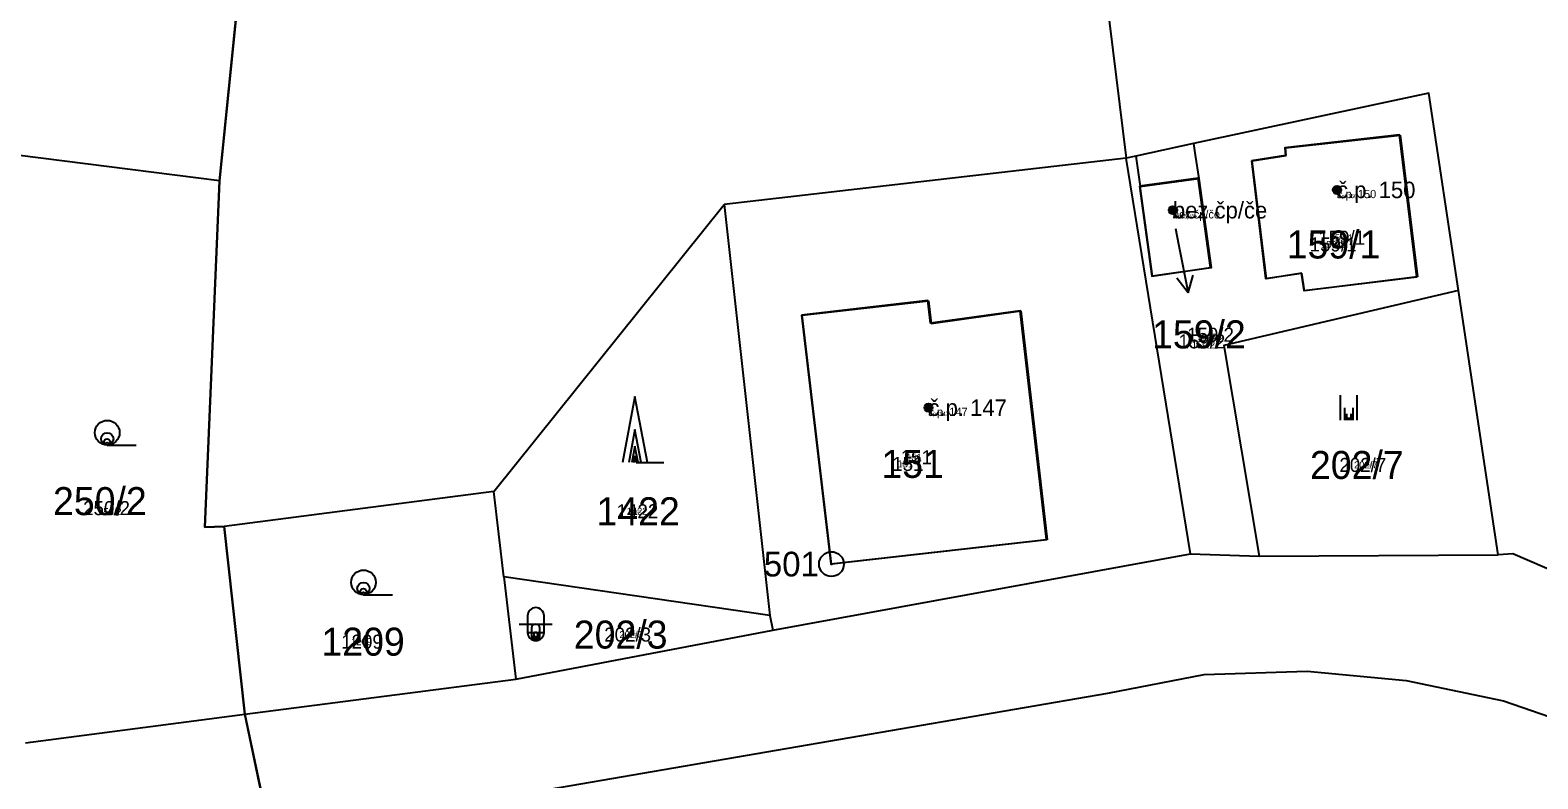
# Model space of a CAD drawing. Extents: x -744652 to -739090, y -980828 to -975855.
# Drawn here: x -741846.2 to -741754.7, y -978833.9 to -978788.5 of the extents above; entities that cross this region are included whole.
import ezdxf

# ---------------------------------------------------------------- set-up
doc = ezdxf.new("R2010")
doc.units = 0
for name, color, linetype in [('KAT_01_hranice KU', 7, 'Continuous'), ('KAT_02_hranice parcel', 7, 'Continuous'), ('KAT_03_1000_st čísla parcelní', 7, 'Continuous'), ('KAT_03_1000_čísla parcelní', 7, 'Continuous'), ('KAT_03_1000_čísla popisná', 7, 'Continuous'), ('KAT_03_100_st čísla parcelní', 7, 'Continuous'), ('KAT_03_100_čísla parcelní', 7, 'Continuous'), ('KAT_03_100_čísla popisná', 7, 'Continuous'), ('KAT_03_250_st čísla parcelní', 7, 'Continuous'), ('KAT_03_250_čísla parcelní', 7, 'Continuous'), ('KAT_03_250_čísla popisná', 7, 'Continuous'), ('KAT_03_500_st čísla parcelní', 7, 'Continuous'), ('KAT_03_500_čísla parcelní', 7, 'Continuous'), ('KAT_03_500_čísla popisná', 7, 'Continuous'), ('KAT_04_vnitřní kresba', 7, 'Continuous'), ('KAT_05_1000_značky kultur', 7, 'Continuous'), ('KAT_05_100_značky kultur', 7, 'Continuous'), ('KAT_05_250_značky kultur', 7, 'Continuous'), ('KAT_05_500_značky kultur', 7, 'Continuous'), ('KAT_07_1000_značky budov', 7, 'Continuous'), ('KAT_07_100_značky budov', 7, 'Continuous'), ('KAT_07_500_značky budov', 7, 'Continuous'), ('KAT_11_značky bodu BP', 7, 'Continuous'), ('KAT_13_popis', 7, 'Continuous'), ('KAT_14_plocha_budovy', 7, 'Continuous')]:
    doc.layers.add(name, color=color, linetype=linetype)

msp = doc.modelspace()

# ---------------------------------------------------------------- linework, layer by layer
at = {"layer": 'KAT_01_hranice KU'}
msp.add_lwpolyline([(-741798.65, -978597.08), (-741808.54, -978644.45), (-741817.44, -978673.77), (-741828.59, -978738.33), (-741829.25, -978742.15), (-741829.42, -978745.8), (-741834.68, -978797.61), (-741835.56, -978818.63), (-741834.39, -978818.59), (-741833.13, -978829.98), (-741831.56, -978837.44), (-741800.71, -978841.57), (-741798.32, -978841.89), (-741797.81, -978844.85), (-741797.75, -978845.17), (-741797.19, -978848.44), (-741793.33, -978870.82), (-741772.86, -978867.41), (-741736.53, -978877.84), (-741709.02, -978891.15), (-741724.37, -978911.25)], dxfattribs=at)
at = {"layer": 'KAT_02_hranice parcel'}
for p, q in [((-741786.56, -978740.39), (-741779.66, -978796.25)), ((-741834.68, -978797.61), (-741829.42, -978745.8)), ((-741834.68, -978797.61), (-741829.42, -978745.8)), ((-741834.68, -978797.61), (-741850.09, -978795.66)), ((-741779.66, -978796.25), (-741804.04, -978799.05)), ((-741775.75, -978820.24), (-741779.66, -978796.25)), ((-741818.02, -978816.47), (-741804.04, -978799.05)), ((-741804.04, -978799.05), (-741801.28, -978823.99)), ((-741757.09, -978820.31), (-741759.49, -978804.27)), ((-741818.02, -978816.47), (-741834.39, -978818.59)), ((-741817.41, -978821.65), (-741818.02, -978816.47)), ((-741833.13, -978829.98), (-741834.39, -978818.59)), ((-741833.13, -978829.98), (-741834.39, -978818.59)), ((-741801.09, -978824.87), (-741775.75, -978820.24)), ((-741775.75, -978820.24), (-741771.59, -978820.39)), ((-741771.59, -978820.39), (-741757.09, -978820.31)), ((-741817.41, -978821.65), (-741816.69, -978827.85)), ((-741801.28, -978823.99), (-741817.41, -978821.65)), ((-741801.28, -978823.99), (-741801.09, -978824.87)), ((-741816.69, -978827.85), (-741801.09, -978824.87)), ((-741833.13, -978829.98), (-741816.69, -978827.85)), ((-741846.45, -978831.72), (-741833.13, -978829.98)), ((-741831.56, -978837.44), (-741833.13, -978829.98)), ((-741831.56, -978837.44), (-741833.13, -978829.98))]:
    msp.add_line(p, q, dxfattribs=at)
for points in [[(-741759.49, -978804.27), (-741761.28, -978792.31), (-741775.56, -978795.36), (-741779.07, -978796.12), (-741779.66, -978796.25)], [(-741834.39, -978818.59), (-741835.56, -978818.63), (-741834.68, -978797.61)], [(-741834.39, -978818.59), (-741835.56, -978818.63), (-741834.68, -978797.61)], [(-741778.06, -978803.41), (-741778.8, -978797.96), (-741775.25, -978797.47), (-741774.49, -978802.89), (-741778.06, -978803.41)], [(-741759.49, -978804.27), (-741773.73, -978807.6), (-741771.59, -978820.39)], [(-741747.63, -978824.34), (-741749.39, -978823.17), (-741756.2, -978820.25), (-741757.09, -978820.31)], [(-741831.56, -978837.44), (-741780.77, -978828.69), (-741774.92, -978827.57), (-741768.67, -978827.36), (-741762.67, -978827.93), (-741756.75, -978829.17), (-741751.07, -978831.13), (-741745.75, -978833.78), (-741726.34, -978844.96)]]:
    msp.add_lwpolyline(points, dxfattribs=at)
at = {"layer": 'KAT_03_1000_čísla popisná'}
for centre in [(-741766.86, -978798.17), (-741776.82, -978799.4), (-741791.65, -978811.38)]:
    msp.add_circle(centre, 0.25, dxfattribs=at)
at = {"layer": 'KAT_03_100_čísla popisná'}
for centre in [(-741766.86, -978798.17), (-741776.82, -978799.4), (-741791.65, -978811.38)]:
    msp.add_circle(centre, 0.025, dxfattribs=at)
at = {"layer": 'KAT_03_250_čísla popisná'}
for centre in [(-741766.86, -978798.17), (-741776.82, -978799.4), (-741791.65, -978811.38)]:
    msp.add_circle(centre, 0.0625, dxfattribs=at)
at = {"layer": 'KAT_03_500_čísla popisná'}
for centre in [(-741766.86, -978798.17), (-741776.82, -978799.4), (-741791.65, -978811.38)]:
    msp.add_circle(centre, 0.125, dxfattribs=at)
at = {"layer": 'KAT_04_vnitřní kresba'}
for p, q in [((-741769.98, -978795.62), (-741763.03, -978794.84)), ((-741763.03, -978794.84), (-741761.97, -978803.45)), ((-741775.56, -978795.36), (-741775.47, -978796.06)), ((-741769.94, -978796.09), (-741769.98, -978795.62)), ((-741779.07, -978796.12), (-741779.01, -978796.55)), ((-741779.01, -978796.55), (-741778.8, -978797.96)), ((-741775.47, -978796.06), (-741775.25, -978797.47)), ((-741772, -978796.41), (-741769.94, -978796.09)), ((-741771.15, -978803.56), (-741772, -978796.41)), ((-741769, -978803.23), (-741771.15, -978803.56)), ((-741768.84, -978804.29), (-741769, -978803.23)), ((-741761.97, -978803.45), (-741768.84, -978804.29)), ((-741799.31, -978805.77), (-741791.64, -978804.89)), ((-741791.64, -978804.89), (-741791.48, -978806.27)), ((-741797.54, -978820.87), (-741799.31, -978805.77)), ((-741791.48, -978806.27), (-741786.04, -978805.51)), ((-741786.04, -978805.51), (-741784.45, -978819.39)), ((-741784.45, -978819.39), (-741797.54, -978820.87))]:
    msp.add_line(p, q, dxfattribs=at)
at = {"layer": 'KAT_05_1000_značky kultur'}
for p, q in [((-741766.641, -978812.13), (-741766.641, -978810.63)), ((-741765.64, -978812.13), (-741765.64, -978810.63)), ((-741809.46, -978810.71), (-741810.21, -978814.71)), ((-741808.71, -978814.71), (-741809.46, -978810.71)), ((-741841.483, -978813.65), (-741839.733, -978813.65)), ((-741808.71, -978814.71), (-741807.714, -978814.71)), ((-741825.933, -978822.73), (-741824.183, -978822.73)), ((-741815.981, -978824.011), (-741815.981, -978825.012)), ((-741814.979, -978825.012), (-741814.979, -978824.011)), ((-741816.481, -978824.511), (-741814.479, -978824.511))]:
    msp.add_line(p, q, dxfattribs=at)
for centre in [(-741841.483, -978812.9), (-741825.933, -978821.98)]:
    msp.add_circle(centre, 0.75, dxfattribs=at)
for centre, start, end in [((-741815.48, -978824.011), 0, 180), ((-741815.48, -978825.011), 180, 359.98789)]:
    msp.add_arc(centre, 0.5, start, end, dxfattribs=at)
at = {"layer": 'KAT_05_100_značky kultur'}
for p, q in [((-741766.181, -978812.13), (-741766.181, -978811.98)), ((-741766.081, -978812.13), (-741766.081, -978811.98)), ((-741841.489, -978813.65), (-741841.314, -978813.65)), ((-741809.46, -978814.31), (-741809.535, -978814.71)), ((-741809.385, -978814.71), (-741809.46, -978814.31)), ((-741809.385, -978814.71), (-741809.285, -978814.71)), ((-741825.939, -978822.73), (-741825.764, -978822.73)), ((-741815.58, -978825.41), (-741815.38, -978825.41)), ((-741815.53, -978825.36), (-741815.53, -978825.46)), ((-741815.43, -978825.46), (-741815.43, -978825.36))]:
    msp.add_line(p, q, dxfattribs=at)
for centre in [(-741841.489, -978813.575), (-741825.939, -978822.655)]:
    msp.add_circle(centre, 0.075, dxfattribs=at)
for centre, start, end in [((-741815.48, -978825.36), 0, 180), ((-741815.48, -978825.46), 180, 359.98789)]:
    msp.add_arc(centre, 0.05, start, end, dxfattribs=at)
at = {"layer": 'KAT_05_250_značky kultur'}
for p, q in [((-741766.258, -978812.13), (-741766.258, -978811.755)), ((-741766.008, -978812.13), (-741766.008, -978811.755)), ((-741841.488, -978813.65), (-741841.051, -978813.65)), ((-741809.46, -978813.71), (-741809.647, -978814.71)), ((-741809.272, -978814.71), (-741809.46, -978813.71)), ((-741809.272, -978814.71), (-741809.024, -978814.71)), ((-741825.938, -978822.73), (-741825.501, -978822.73)), ((-741815.73, -978825.26), (-741815.23, -978825.26)), ((-741815.605, -978825.135), (-741815.605, -978825.385)), ((-741815.355, -978825.385), (-741815.355, -978825.135))]:
    msp.add_line(p, q, dxfattribs=at)
for centre in [(-741841.488, -978813.462), (-741825.938, -978822.542)]:
    msp.add_circle(centre, 0.187, dxfattribs=at)
for centre, start, end in [((-741815.48, -978825.135), 0, 180), ((-741815.48, -978825.385), 180, 359.98789)]:
    msp.add_arc(centre, 0.125, start, end, dxfattribs=at)
at = {"layer": 'KAT_05_500_značky kultur'}
for p, q in [((-741766.385, -978812.13), (-741766.385, -978811.38)), ((-741765.885, -978812.13), (-741765.885, -978811.38)), ((-741809.46, -978812.71), (-741809.835, -978814.71)), ((-741809.085, -978814.71), (-741809.46, -978812.71)), ((-741841.486, -978813.65), (-741840.611, -978813.65)), ((-741809.085, -978814.71), (-741808.587, -978814.71)), ((-741825.937, -978822.73), (-741825.062, -978822.73)), ((-741815.981, -978825.01), (-741814.98, -978825.01)), ((-741815.731, -978824.76), (-741815.731, -978825.261)), ((-741815.23, -978825.261), (-741815.23, -978824.76))]:
    msp.add_line(p, q, dxfattribs=at)
for centre in [(-741841.486, -978813.275), (-741825.936, -978822.355)]:
    msp.add_circle(centre, 0.375, dxfattribs=at)
for centre, start, end in [((-741815.48, -978824.76), 0, 180), ((-741815.48, -978825.26), 180, 359.98789)]:
    msp.add_arc(centre, 0.25, start, end, dxfattribs=at)
at = {"layer": 'KAT_07_1000_značky budov'}
for centre in [(-741766.867, -978798.169), (-741776.827, -978799.399), (-741791.657, -978811.379)]:
    msp.add_circle(centre, 0.175, dxfattribs=at)
at = {"layer": 'KAT_07_100_značky budov'}
for centre in [(-741766.861, -978798.17), (-741776.821, -978799.4), (-741791.651, -978811.38)]:
    msp.add_circle(centre, 0.0175, dxfattribs=at)
at = {"layer": 'KAT_07_500_značky budov'}
for centre in [(-741766.863, -978798.17), (-741776.823, -978799.4), (-741791.653, -978811.38)]:
    msp.add_circle(centre, 0.0875, dxfattribs=at)
at = {"layer": 'KAT_11_značky bodu BP'}
for radius in [0.75, 0.03]:
    msp.add_circle((-741797.54, -978820.87), radius, dxfattribs=at)
at = {"layer": 'KAT_13_popis'}
for p, q in [((-741776.66, -978800.51), (-741776.47, -978801.47)), ((-741776.47, -978801.47), (-741775.897, -978804.416)), ((-741775.897, -978804.416), (-741775.597, -978803.337)), ((-741775.897, -978804.416), (-741776.58, -978803.528))]:
    msp.add_line(p, q, dxfattribs=at)
at = {"layer": 'KAT_14_plocha_budovy'}
for points in [[(-741772.041, -978796.399), (-741771.191, -978803.549), (-741769.041, -978803.219), (-741768.881, -978804.279), (-741762.011, -978803.439), (-741763.071, -978794.829), (-741770.021, -978795.609), (-741769.981, -978796.079)], [(-741778.841, -978797.949), (-741778.101, -978803.399), (-741774.531, -978802.879), (-741775.291, -978797.459)], [(-741799.351, -978805.759), (-741797.581, -978820.859), (-741784.491, -978819.379), (-741786.081, -978805.499), (-741791.521, -978806.259), (-741791.681, -978804.879)]]:
    msp.add_lwpolyline(points, close=True, dxfattribs=at)

# ---------------------------------------------------------------- texts
at = {"layer": 'KAT_03_1000_st čísla parcelní'}
for s, p in [('159/1', (-741769.915, -978802.33)), ('159/2', (-741778.085, -978807.784)), ('151', (-741794.506, -978815.64))]:
    msp.add_text(s, height=1.7, dxfattribs=at).set_placement(p)
at = {"layer": 'KAT_03_1000_čísla parcelní'}
for s, p in [('202/7', (-741768.503, -978815.706)), ('250/2', (-741844.773, -978817.9)), ('1422', (-741811.797, -978818.516)), ('202/3', (-741813.173, -978825.996)), ('1209', (-741828.487, -978826.426))]:
    msp.add_text(s, height=1.7, dxfattribs=at).set_placement(p)
at = {"layer": 'KAT_03_1000_čísla popisná'}
for s, p in [('č.p. 150', (-741766.86, -978798.67)), ('bez čp/če', (-741776.82, -978799.9)), ('č.p. 147', (-741791.65, -978811.88))]:
    msp.add_text(s, height=1, dxfattribs=at).set_placement(p)
at = {"layer": 'KAT_03_100_st čísla parcelní'}
for s, p in [('159/1', (-741767.409, -978801.565)), ('159/2', (-741775.2, -978807.784)), ('151', (-741793.331, -978814.875))]:
    msp.add_text(s, height=0.17, dxfattribs=at).set_placement(p)
at = {"layer": 'KAT_03_100_čísla parcelní'}
for s, p in [('159/1', (-741766.887, -978801.161)), ('159/2', (-741774.678, -978807.38)), ('151', (-741792.81, -978814.471)), ('202/7', (-741765.293, -978814.941)), ('250/2', (-741841.484, -978817.9)), ('1422', (-741809.599, -978817.751)), ('202/3', (-741809.848, -978825.231)), ('1209', (-741826.331, -978825.661))]:
    msp.add_text(s, height=0.17, dxfattribs=at).set_placement(p)
at = {"layer": 'KAT_03_100_čísla popisná'}
for s, p in [('č.p. 150', (-741766.86, -978798.67)), ('bez čp/če', (-741776.82, -978799.9)), ('č.p. 147', (-741791.65, -978811.88))]:
    msp.add_text(s, height=0.1, dxfattribs=at).set_placement(p)
at = {"layer": 'KAT_03_250_st čísla parcelní'}
for s, p in [('159/1', (-741767.827, -978801.692)), ('159/2', (-741775.681, -978807.784)), ('151', (-741793.527, -978815.002))]:
    msp.add_text(s, height=0.425, dxfattribs=at).set_placement(p)
at = {"layer": 'KAT_03_250_čísla parcelní'}
for s, p in [('159/1', (-741767.305, -978801.289)), ('159/2', (-741775.159, -978807.38)), ('151', (-741793.005, -978814.599)), ('202/7', (-741765.828, -978815.069)), ('250/2', (-741842.032, -978817.9)), ('1422', (-741809.965, -978817.879)), ('202/3', (-741810.402, -978825.359)), ('1209', (-741826.69, -978825.789))]:
    msp.add_text(s, height=0.425, dxfattribs=at).set_placement(p)
at = {"layer": 'KAT_03_250_čísla popisná'}
for s, p in [('č.p. 150', (-741766.86, -978798.67)), ('bez čp/če', (-741776.82, -978799.9)), ('č.p. 147', (-741791.65, -978811.88))]:
    msp.add_text(s, height=0.25, dxfattribs=at).set_placement(p)
at = {"layer": 'KAT_03_500_st čísla parcelní'}
for s, p in [('159/1', (-741768.523, -978801.905)), ('159/2', (-741776.482, -978807.784)), ('151', (-741793.853, -978815.215))]:
    msp.add_text(s, height=0.85, dxfattribs=at).set_placement(p)
at = {"layer": 'KAT_03_500_čísla parcelní'}
for s, p in [('159/1', (-741768.001, -978801.501)), ('159/2', (-741775.96, -978807.38)), ('151', (-741793.332, -978814.811)), ('202/7', (-741766.719, -978815.281)), ('250/2', (-741842.946, -978817.9)), ('1422', (-741810.576, -978818.091)), ('1209', (-741827.289, -978826.001)), ('202/3', (-741811.326, -978825.571))]:
    msp.add_text(s, height=0.85, dxfattribs=at).set_placement(p)
at = {"layer": 'KAT_03_500_čísla popisná'}
for s, p in [('č.p. 150', (-741766.86, -978798.67)), ('bez čp/če', (-741776.82, -978799.9)), ('č.p. 147', (-741791.65, -978811.88))]:
    msp.add_text(s, height=0.5, dxfattribs=at).set_placement(p)
at = {"layer": 'KAT_11_značky bodu BP'}
msp.add_text('501', height=1.5, dxfattribs=at).set_placement((-741801.643, -978821.62))

doc.saveas('drawing.dxf')
